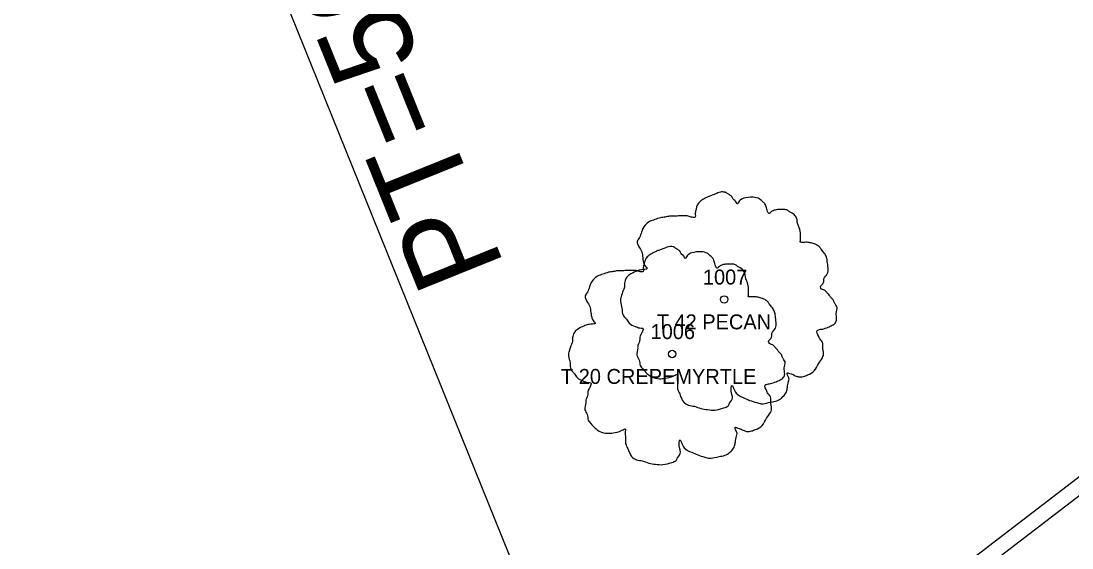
# Model space of a CAD drawing. Extents: x 1964982 to 1970452, y 1116335 to 1119906.
# Drawn here: x 1966719.9 to 1966790.2, y 1117493.6 to 1117528.9 of the extents above; entities that cross this region are included whole.
import ezdxf

# ---------------------------------------------------------------- set-up
doc = ezdxf.new("R2010")
doc.units = 0
for name, color, linetype in [('RD_EX_VEG', 7, 'Continuous'), ('RD_EX_VEG_txCode', 7, 'Continuous'), ('RD_HC_Data', 7, 'Continuous'), ('RD_PD_CstnLmt', 7, 'Continuous'), ('RD_PD_Final_TrvlWay', 7, 'Continuous'), ('RD_PD_RW', 7, 'Continuous')]:
    doc.layers.add(name, color=color, linetype=linetype)

msp = doc.modelspace()

# ---------------------------------------------------------------- linework, layer by layer
at = {"layer": 'RD_EX_VEG'}
for centre, radius in [((1966766.925, 1117510.253), 0.25), ((1966766.913, 1117510.234), 0.0001), ((1966763.446, 1117506.601), 0.25), ((1966763.434, 1117506.582), 0.0001)]:
    msp.add_circle(centre, radius, dxfattribs=at)
for points in [[(1966767.057, 1117517.42), (1966766.757, 1117517.445), (1966766.432, 1117517.345), (1966766.183, 1117517.245), (1966765.958, 1117517.17), (1966765.733, 1117517.07), (1966765.433, 1117516.896), (1966765.208, 1117516.696), (1966765.083, 1117516.446), (1966765.033, 1117516.221), (1966764.983, 1117515.946), (1966764.983, 1117515.771), (1966764.858, 1117515.746), (1966764.708, 1117515.771), (1966764.458, 1117515.846), (1966764.208, 1117515.846), (1966763.958, 1117515.846), (1966763.609, 1117515.821), (1966763.259, 1117515.821), (1966762.984, 1117515.771), (1966762.659, 1117515.721), (1966762.284, 1117515.596), (1966761.934, 1117515.471), (1966761.635, 1117515.221), (1966761.385, 1117514.747), (1966761.26, 1117514.397), (1966761.11, 1117514.147), (1966761.26, 1117513.697), (1966761.435, 1117513.347), (1966761.46, 1117513.147), (1966761.535, 1117512.722), (1966761.635, 1117512.498), (1966761.759, 1117512.298), (1966761.685, 1117512.273), (1966761.31, 1117512.223), (1966761.01, 1117512.123), (1966760.585, 1117511.898), (1966760.36, 1117511.673), (1966760.26, 1117511.348), (1966760.235, 1117510.998), (1966760.135, 1117510.798), (1966760.06, 1117510.523), (1966760.035, 1117510.448), (1966759.985, 1117510.124), (1966760.085, 1117509.674), (1966760.11, 1117509.324), (1966760.235, 1117509.099), (1966760.385, 1117508.924), (1966760.56, 1117508.674), (1966760.96, 1117508.449), (1966761.285, 1117508.349), (1966761.485, 1117508.324), (1966761.31, 1117507.825), (1966761.26, 1117507.475), (1966761.135, 1117507.075), (1966761.135, 1117507), (1966761.085, 1117506.525), (1966761.235, 1117506.2), (1966761.31, 1117505.825), (1966761.485, 1117505.601), (1966761.759, 1117505.301), (1966762.084, 1117505.076), (1966762.584, 1117504.951), (1966762.984, 1117504.976), (1966763.559, 1117505.151), (1966763.809, 1117505.226), (1966763.784, 1117505.051), (1966763.809, 1117504.676), (1966763.809, 1117504.251), (1966763.958, 1117503.926), (1966764.058, 1117503.651), (1966764.208, 1117503.401), (1966764.533, 1117503.177), (1966764.933, 1117503.102), (1966765.358, 1117502.952), (1966765.808, 1117502.877), (1966766.307, 1117502.852), (1966766.907, 1117503.002), (1966767.182, 1117503.127), (1966767.282, 1117503.302), (1966767.482, 1117503.676), (1966767.432, 1117503.901), (1966767.457, 1117504.501), (1966767.557, 1117504.326), (1966767.732, 1117503.976), (1966768.232, 1117503.676), (1966768.631, 1117503.501), (1966769.106, 1117503.351), (1966769.406, 1117503.277), (1966769.881, 1117503.351), (1966770.256, 1117503.426), (1966770.631, 1117503.551), (1966770.93, 1117503.826), (1966771.105, 1117504.101), (1966771.155, 1117504.376), (1966771.23, 1117504.751), (1966771.28, 1117504.926)], [(1966771.28, 1117504.926), (1966771.205, 1117505.101), (1966771.155, 1117505.351), (1966771.23, 1117505.326), (1966771.405, 1117505.276), (1966771.68, 1117505.151), (1966771.905, 1117505.076), (1966772.23, 1117505.101), (1966772.505, 1117505.201), (1966772.955, 1117505.476), (1966773.229, 1117505.95), (1966773.504, 1117506.35), (1966773.579, 1117506.675), (1966773.529, 1117506.9), (1966773.504, 1117507.4), (1966773.304, 1117507.65), (1966773.254, 1117507.775), (1966773.154, 1117508.174), (1966773.229, 1117508.224), (1966773.504, 1117508.274), (1966773.879, 1117508.399), (1966774.154, 1117508.524), (1966774.379, 1117508.699), (1966774.454, 1117508.924), (1966774.429, 1117509.324), (1966774.479, 1117509.724), (1966774.404, 1117509.874), (1966774.304, 1117510.024), (1966774.229, 1117510.224), (1966774.079, 1117510.373), (1966773.979, 1117510.523), (1966773.879, 1117510.623), (1966773.754, 1117510.773), (1966773.579, 1117510.898), (1966773.429, 1117510.948), (1966773.379, 1117511.098), (1966773.529, 1117511.298), (1966773.579, 1117511.398), (1966773.604, 1117511.623), (1966773.829, 1117511.973), (1966773.879, 1117512.373), (1966773.829, 1117512.797), (1966773.779, 1117513.072), (1966773.629, 1117513.347), (1966773.429, 1117513.597), (1966773.304, 1117513.772), (1966773.129, 1117513.897), (1966772.805, 1117514.022), (1966772.555, 1117514.072), (1966772.205, 1117514.072), (1966772.005, 1117514.122), (1966772.03, 1117514.172), (1966772.03, 1117514.322), (1966772.03, 1117514.597), (1966771.955, 1117515.046), (1966771.805, 1117515.546), (1966771.805, 1117515.571), (1966771.705, 1117515.821), (1966771.48, 1117516.021), (1966771.305, 1117516.121), (1966771.105, 1117516.246), (1966770.855, 1117516.271), (1966770.556, 1117516.271), (1966770.281, 1117516.221), (1966770.081, 1117516.121), (1966769.906, 1117515.996), (1966769.831, 1117516.146), (1966769.731, 1117516.446), (1966769.681, 1117516.596), (1966769.531, 1117516.771), (1966769.306, 1117516.971), (1966768.856, 1117517.095), (1966768.232, 1117517.021), (1966767.932, 1117516.821), (1966767.782, 1117516.646), (1966767.732, 1117516.771), (1966767.532, 1117516.971), (1966767.432, 1117517.145), (1966767.257, 1117517.27), (1966767.107, 1117517.37), (1966767.007, 1117517.42)], [(1966763.578, 1117513.768), (1966763.278, 1117513.793), (1966762.954, 1117513.693), (1966762.704, 1117513.594), (1966762.479, 1117513.519), (1966762.254, 1117513.419), (1966761.954, 1117513.244), (1966761.729, 1117513.044), (1966761.604, 1117512.794), (1966761.554, 1117512.569), (1966761.504, 1117512.294), (1966761.504, 1117512.119), (1966761.379, 1117512.094), (1966761.229, 1117512.119), (1966760.979, 1117512.194), (1966760.73, 1117512.194), (1966760.48, 1117512.194), (1966760.13, 1117512.169), (1966759.78, 1117512.169), (1966759.505, 1117512.119), (1966759.18, 1117512.069), (1966758.805, 1117511.944), (1966758.456, 1117511.819), (1966758.156, 1117511.569), (1966757.906, 1117511.095), (1966757.781, 1117510.745), (1966757.631, 1117510.495), (1966757.781, 1117510.045), (1966757.956, 1117509.695), (1966757.981, 1117509.495), (1966758.056, 1117509.071), (1966758.156, 1117508.846), (1966758.281, 1117508.646), (1966758.206, 1117508.621), (1966757.831, 1117508.571), (1966757.531, 1117508.471), (1966757.106, 1117508.246), (1966756.881, 1117508.021), (1966756.781, 1117507.696), (1966756.756, 1117507.346), (1966756.656, 1117507.146), (1966756.581, 1117506.871), (1966756.556, 1117506.796), (1966756.506, 1117506.472), (1966756.606, 1117506.022), (1966756.631, 1117505.672), (1966756.756, 1117505.447), (1966756.906, 1117505.272), (1966757.081, 1117505.022), (1966757.481, 1117504.797), (1966757.806, 1117504.697), (1966758.006, 1117504.672), (1966757.831, 1117504.173), (1966757.781, 1117503.823), (1966757.656, 1117503.423), (1966757.656, 1117503.348), (1966757.606, 1117502.873), (1966757.756, 1117502.548), (1966757.831, 1117502.174), (1966758.006, 1117501.949), (1966758.281, 1117501.649), (1966758.605, 1117501.424), (1966759.105, 1117501.299), (1966759.505, 1117501.324), (1966760.08, 1117501.499), (1966760.33, 1117501.574), (1966760.305, 1117501.399), (1966760.33, 1117501.024), (1966760.33, 1117500.599), (1966760.48, 1117500.274), (1966760.58, 1117499.999), (1966760.73, 1117499.75), (1966761.054, 1117499.525), (1966761.454, 1117499.45), (1966761.879, 1117499.3), (1966762.329, 1117499.225), (1966762.829, 1117499.2), (1966763.428, 1117499.35), (1966763.703, 1117499.475), (1966763.803, 1117499.65), (1966764.003, 1117500.024), (1966763.953, 1117500.249), (1966763.978, 1117500.849), (1966764.078, 1117500.674), (1966764.253, 1117500.324), (1966764.753, 1117500.024), (1966765.153, 1117499.85), (1966765.627, 1117499.7), (1966765.927, 1117499.625), (1966766.402, 1117499.7), (1966766.777, 1117499.775), (1966767.152, 1117499.9), (1966767.452, 1117500.174), (1966767.627, 1117500.449), (1966767.677, 1117500.724), (1966767.751, 1117501.099), (1966767.801, 1117501.274)], [(1966767.801, 1117501.274), (1966767.727, 1117501.449), (1966767.677, 1117501.699), (1966767.751, 1117501.674), (1966767.926, 1117501.624), (1966768.201, 1117501.499), (1966768.426, 1117501.424), (1966768.751, 1117501.449), (1966769.026, 1117501.549), (1966769.476, 1117501.824), (1966769.751, 1117502.298), (1966770.025, 1117502.698), (1966770.1, 1117503.023), (1966770.05, 1117503.248), (1966770.025, 1117503.748), (1966769.826, 1117503.998), (1966769.776, 1117504.123), (1966769.676, 1117504.522), (1966769.751, 1117504.572), (1966770.025, 1117504.622), (1966770.4, 1117504.747), (1966770.675, 1117504.872), (1966770.9, 1117505.047), (1966770.975, 1117505.272), (1966770.95, 1117505.672), (1966771, 1117506.072), (1966770.925, 1117506.222), (1966770.825, 1117506.372), (1966770.75, 1117506.572), (1966770.6, 1117506.721), (1966770.5, 1117506.871), (1966770.4, 1117506.971), (1966770.275, 1117507.121), (1966770.1, 1117507.246), (1966769.951, 1117507.296), (1966769.901, 1117507.446), (1966770.05, 1117507.646), (1966770.1, 1117507.746), (1966770.125, 1117507.971), (1966770.35, 1117508.321), (1966770.4, 1117508.721), (1966770.35, 1117509.145), (1966770.3, 1117509.42), (1966770.15, 1117509.695), (1966769.951, 1117509.945), (1966769.826, 1117510.12), (1966769.651, 1117510.245), (1966769.326, 1117510.37), (1966769.076, 1117510.42), (1966768.726, 1117510.42), (1966768.526, 1117510.47), (1966768.551, 1117510.52), (1966768.551, 1117510.67), (1966768.551, 1117510.945), (1966768.476, 1117511.394), (1966768.326, 1117511.894), (1966768.326, 1117511.919), (1966768.226, 1117512.169), (1966768.001, 1117512.369), (1966767.826, 1117512.469), (1966767.627, 1117512.594), (1966767.377, 1117512.619), (1966767.077, 1117512.619), (1966766.802, 1117512.569), (1966766.602, 1117512.469), (1966766.427, 1117512.344), (1966766.352, 1117512.494), (1966766.252, 1117512.794), (1966766.202, 1117512.944), (1966766.052, 1117513.119), (1966765.827, 1117513.319), (1966765.377, 1117513.444), (1966764.753, 1117513.369), (1966764.453, 1117513.169), (1966764.303, 1117512.994), (1966764.253, 1117513.119), (1966764.053, 1117513.319), (1966763.953, 1117513.494), (1966763.778, 1117513.619), (1966763.628, 1117513.718), (1966763.528, 1117513.768)]]:
    msp.add_spline(points, degree=3, dxfattribs=at)
at = {"layer": 'RD_HC_Data'}
msp.add_line((1966770.74, 1117448.117), (1966733.843, 1117539.46), dxfattribs=at)
at = {"layer": 'RD_PD_CstnLmt'}
msp.add_line((1966801.626, 1117505.485), (1966761.449, 1117474.738), dxfattribs=at)
at = {"layer": 'RD_PD_Final_TrvlWay'}
msp.add_arc((1966373.74, 1118527.456), 1134.915, 281.904723, 295.046328, dxfattribs=at)
at = {"layer": 'RD_PD_RW'}
msp.add_line((1966801.061, 1117506.313), (1966760.987, 1117475.643), dxfattribs=at)

# ---------------------------------------------------------------- texts
at = {"layer": 'RD_EX_VEG_txCode'}
for s, p in [('1007', (1966765.5, 1117511.253)), ('1006', (1966761.998, 1117507.601)), ('T 42 PECAN', (1966762.413, 1117508.253)), ('T 20 CREPEMYRTLE', (1966756.002, 1117504.601))]:
    msp.add_text(s, height=1, dxfattribs=at).set_placement(p)
at = {"layer": 'RD_HC_Data'}
msp.add_text('PT=50+00.00', height=6, rotation=111.99584, dxfattribs=at).set_placement((1966752.259, 1117512.485))

doc.saveas('drawing.dxf')
